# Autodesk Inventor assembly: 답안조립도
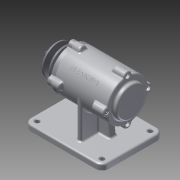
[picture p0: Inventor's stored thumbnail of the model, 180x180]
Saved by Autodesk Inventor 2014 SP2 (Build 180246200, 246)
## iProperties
Created: 2015-12
Part Number: 답안조립도
Document SubType Name: Assembly
Designer: Administrator
Author: Administrator
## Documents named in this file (11)
- C:\Users\Administrator\Desktop\451207V1009\답안조립도.iam
- C:\Users\Administrator\Desktop\451207V1009\본체.ipt
- C:\Users\Administrator\Desktop\451207V1009\V-벨트풀리.ipt
- C:\Users\Administrator\Desktop\451207V1009\너트 M12x1.25.ipt
- C:\Users\Administrator\Desktop\451207V1009\베어링 6204.ipt
- C:\Users\Administrator\Desktop\451207V1009\볼트 M4 x 12.ipt
- C:\Users\Administrator\Desktop\451207V1009\오일실.ipt
- C:\Users\Administrator\Desktop\451207V1009\축.ipt
- C:\Users\Administrator\Desktop\451207V1009\커버.ipt
- C:\Users\Administrator\Desktop\451207V1009\커버2.ipt
- C:\Users\Administrator\Desktop\451207V1009\키(4 x 4 x 12).ipt
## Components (6 placed, 5 different names)
1. V-벨트풀리:1
2. KS B 1012 클래스 1 일반 - 미터 M12x1.25:1
3. KS B 2023 6204 - 20 x 47 x 14:1
4. KS B 2023 6204 - 20 x 47 x 14:2
5. KS B 2804 D D - 20 32 8:1
6. KS B 1311 (I) 4 x 4 x 12:1
